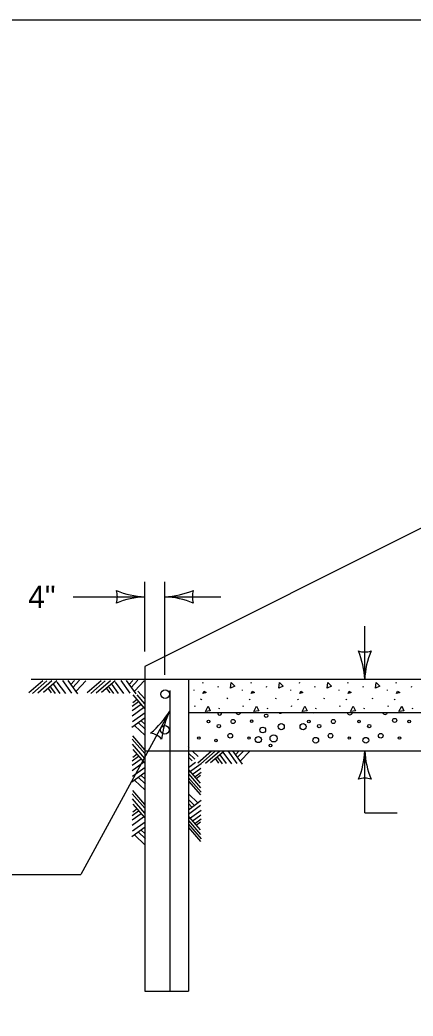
# Model space of a CAD drawing. Extents: x 49991.4 to 50021, y 49987.6 to 50011.4.
# Drawn here: x 50011.844 to 50012.898, y 49989.416 to 49992.087 of the extents above; entities that cross this region are included whole.
import ezdxf

# ---------------------------------------------------------------- set-up
doc = ezdxf.new("R2010")
doc.units = 0
for name, color, linetype in [('Level 1', 7, 'Continuous'), ('Level 2', 7, 'Continuous'), ('Level 3', 7, 'Continuous')]:
    doc.layers.add(name, color=color, linetype=linetype)

msp = doc.modelspace()

# ---------------------------------------------------------------- linework, layer by layer
at = {"layer": 'Level 1'}
for p, q in [((50013.9584, 49991.2434), (50012.1786, 49990.3535)), ((50012.1786, 49990.3535), (50012.1786, 49989.4831)), ((50011.9052, 49990.3145), (50011.8682, 49990.2823)), ((50011.8745, 49990.3188), (50012.2956, 49990.3188)), ((50011.9161, 49990.3145), (50011.8772, 49990.2806)), ((50011.9299, 49990.3147), (50011.8919, 49990.2816)), ((50011.9431, 49990.3149), (50011.9068, 49990.2833)), ((50011.9336, 49990.305), (50011.9509, 49990.2812)), ((50011.9432, 49990.3115), (50011.9658, 49990.2806)), ((50011.9579, 49990.3153), (50011.9824, 49990.2816)), ((50011.9722, 49990.3155), (50011.9982, 49990.2798)), ((50011.9792, 49990.304), (50011.99, 49990.3155)), ((50011.9857, 49990.2972), (50012.004, 49990.3165)), ((50011.9952, 49990.2881), (50012.0206, 49990.3151)), ((50012.0616, 49990.3145), (50012.0245, 49990.2823)), ((50012.0725, 49990.3145), (50012.0336, 49990.2806)), ((50012.0863, 49990.3147), (50012.0482, 49990.2816)), ((50012.0995, 49990.3149), (50012.063, 49990.2833)), ((50012.0899, 49990.305), (50012.1073, 49990.2812)), ((50012.0995, 49990.3115), (50012.122, 49990.2806)), ((50012.1141, 49990.3153), (50012.1387, 49990.2816)), ((50012.1284, 49990.3155), (50012.1546, 49990.2798)), ((50012.1355, 49990.304), (50012.1463, 49990.3155)), ((50012.142, 49990.2972), (50012.1602, 49990.3165)), ((50012.1516, 49990.2881), (50012.177, 49990.3151)), ((50012.1786, 49990.3145), (50012.1786, 49990.3145)), ((50012.2956, 49990.3188), (50012.2956, 49989.4831)), ((50012.2956, 49990.3188), (50014.2581, 49990.3188)), ((50011.9196, 49990.2939), (50011.9281, 49990.2822)), ((50011.9258, 49990.2978), (50011.9383, 49990.2806)), ((50012.076, 49990.2939), (50012.0845, 49990.2822)), ((50012.0822, 49990.2978), (50012.0947, 49990.2806)), ((50012.179, 49990.241), (50012.1474, 49990.2774)), ((50012.1788, 49990.2534), (50012.1583, 49990.2769)), ((50012.1786, 49990.2662), (50012.1604, 49990.2871)), ((50012.2454, 49990.2888), (50012.2454, 49989.4831)), ((50012.2956, 49990.279), (50012.2956, 49990.279)), ((50012.1618, 49990.2588), (50012.1447, 49990.2462)), ((50012.169, 49990.2516), (50012.1452, 49990.2343)), ((50012.1579, 49990.2644), (50012.1463, 49990.2559)), ((50012.1756, 49990.2428), (50012.1447, 49990.2203)), ((50012.1793, 49990.2291), (50012.1457, 49990.2045)), ((50012.2956, 49990.2297), (50014.2581, 49990.2297)), ((50012.1796, 49990.2157), (50012.1439, 49990.1897)), ((50012.1522, 49990.1941), (50012.179, 49990.1687)), ((50012.1613, 49990.2029), (50012.1806, 49990.1845)), ((50012.1681, 49990.2086), (50012.1795, 49990.1978)), ((50012.1786, 49990.13), (50012.1463, 49990.167)), ((50012.1786, 49990.1197), (50012.1447, 49990.1586)), ((50012.1788, 49990.1067), (50012.1457, 49990.1448)), ((50012.1618, 49990.1123), (50012.1447, 49990.0997)), ((50012.1579, 49990.1179), (50012.1463, 49990.1094)), ((50012.179, 49990.0945), (50012.1474, 49990.1309)), ((50012.1786, 49990.1273), (50014.2581, 49990.1273)), ((50012.3128, 49990.1049), (50012.2956, 49990.1212)), ((50012.322, 49990.1119), (50012.3057, 49990.1273)), ((50012.3576, 49990.1262), (50012.3206, 49990.0939)), ((50012.3674, 49990.1262), (50012.3285, 49990.0922)), ((50012.3797, 49990.1263), (50012.3416, 49990.0932)), ((50012.3913, 49990.1266), (50012.3549, 49990.0948)), ((50012.3799, 49990.1166), (50012.3972, 49990.0928)), ((50012.3882, 49990.1232), (50012.4107, 49990.0923)), ((50012.4011, 49990.1269), (50012.4256, 49990.0933)), ((50012.4137, 49990.1271), (50012.4398, 49990.0915)), ((50012.4208, 49990.1157), (50012.4316, 49990.1271)), ((50012.4262, 49990.1088), (50012.4437, 49990.1273)), ((50012.4343, 49990.0996), (50012.4598, 49990.1266)), ((50012.1756, 49990.0962), (50012.1447, 49990.0736)), ((50012.169, 49990.1051), (50012.1452, 49990.0878)), ((50012.306, 49990.1005), (50012.2956, 49990.1104)), ((50012.2956, 49990.0826), (50012.3145, 49990.0964)), ((50012.2986, 49990.0706), (50012.3294, 49990.0931)), ((50012.3679, 49990.1055), (50012.3764, 49990.0939)), ((50012.3733, 49990.1094), (50012.3858, 49990.0922)), ((50012.1796, 49990.0692), (50012.1439, 49990.0431)), ((50012.1793, 49990.0825), (50012.1457, 49990.058)), ((50012.1681, 49990.0621), (50012.1795, 49990.0513)), ((50012.2956, 49990.0758), (50012.3268, 49990.04)), ((50012.2956, 49990.0658), (50012.3284, 49990.028)), ((50012.3052, 49990.0634), (50012.3289, 49990.0807)), ((50012.3124, 49990.0577), (50012.3294, 49990.0701)), ((50012.3162, 49990.0531), (50012.3278, 49990.0616)), ((50012.1522, 49990.0476), (50012.179, 49990.0221)), ((50012.1613, 49990.0562), (50012.1806, 49990.038)), ((50012.2956, 49990.055), (50012.3294, 49990.0163)), ((50012.2956, 49990.0461), (50012.3278, 49990.0092)), ((50012.1786, 49989.9732), (50012.1447, 49990.0121)), ((50012.1786, 49989.9835), (50012.1463, 49990.0205)), ((50012.322, 49989.9869), (50012.2956, 49990.0118)), ((50012.1788, 49989.9602), (50012.1457, 49989.9983)), ((50012.179, 49989.948), (50012.1474, 49989.9843)), ((50012.3128, 49989.98), (50012.2956, 49989.9963)), ((50012.2956, 49989.9692), (50012.3302, 49989.9944)), ((50012.306, 49989.9756), (50012.2956, 49989.9855)), ((50012.2956, 49989.9577), (50012.3284, 49989.9817)), ((50012.1618, 49989.9656), (50012.1447, 49989.9531)), ((50012.169, 49989.9585), (50012.1452, 49989.9411)), ((50012.1579, 49989.9714), (50012.1463, 49989.9629)), ((50012.2986, 49989.9456), (50012.3294, 49989.9681)), ((50012.3052, 49989.9384), (50012.3289, 49989.9558)), ((50012.1756, 49989.9497), (50012.1447, 49989.9271)), ((50012.1793, 49989.936), (50012.1457, 49989.9115)), ((50012.2956, 49989.9509), (50012.3268, 49989.915)), ((50012.2956, 49989.9407), (50012.3284, 49989.903)), ((50012.2956, 49989.9301), (50012.3294, 49989.8912)), ((50012.3124, 49989.9327), (50012.3294, 49989.9452)), ((50012.3162, 49989.9282), (50012.3278, 49989.9367)), ((50012.1796, 49989.9227), (50012.1439, 49989.8966)), ((50012.1522, 49989.9011), (50012.179, 49989.8755)), ((50012.1613, 49989.9097), (50012.1806, 49989.8915)), ((50012.1681, 49989.9156), (50012.1795, 49989.9048)), ((50012.2956, 49989.9212), (50012.3278, 49989.8841)), ((50012.1786, 49989.7217), (50012.1786, 49989.7217)), ((50012.1786, 49989.4831), (50012.2956, 49989.4831))]:
    msp.add_line(p, q, dxfattribs=at)
msp.add_lwpolyline([(49999.5517, 49992.0867), (50014.5753, 49992.0867), (50014.5753, 49988.387), (49999.5517, 49988.387)], close=True, dxfattribs=at)
for centre, radius in [((50012.233, 49990.2792), 0.0116), ((50012.504, 49990.2212), 0.0046), ((50012.2325, 49990.1836), 0.0116), ((50012.3496, 49990.2058), 0.00341), ((50012.3771, 49990.1935), 0.0046), ((50012.4154, 49990.2058), 0.00552), ((50012.4651, 49990.2066), 0.00341), ((50012.5443, 49990.192), 0.00824), ((50012.6031, 49990.192), 0.00824), ((50012.6184, 49990.2058), 0.00341), ((50012.646, 49990.1935), 0.0046), ((50012.6843, 49990.2058), 0.00552), ((50012.7529, 49990.2058), 0.00341), ((50012.7804, 49990.1935), 0.0046), ((50012.8484, 49990.2086), 0.00552), ((50012.8873, 49990.2058), 0.00341), ((50012.3235, 49990.1615), 0.00341), ((50012.4077, 49990.1676), 0.00613), ((50012.458, 49990.1615), 0.00341), ((50012.4832, 49990.1573), 0.00824), ((50012.4948, 49990.183), 0.00766), ((50012.524, 49990.1605), 0.00968), ((50012.6766, 49990.1676), 0.00613), ((50012.7268, 49990.1615), 0.00341), ((50012.8111, 49990.1676), 0.00613), ((50012.8613, 49990.1615), 0.00341), ((50012.3695, 49990.1548), 0.00341), ((50012.5155, 49990.1413), 0.00341), ((50012.6368, 49990.1554), 0.00766), ((50012.7712, 49990.1554), 0.00766)]:
    msp.add_circle(centre, radius, dxfattribs=at)
for centre, radius, start, end in [((50012.3794, 49990.2286), 0.00552, 168.5096, 11.4904), ((50012.4296, 49990.2326), 0.00765, 202.8197, 337.1803), ((50012.5423, 49990.2334), 0.00552, 222.7241, 317.2759), ((50012.6305, 49990.2355), 0.00684, 238.3741, 301.6259), ((50012.7284, 49990.2317), 0.00765, 195.3909, 344.6091), ((50012.8228, 49990.2326), 0.00765, 202.8197, 337.1803), ((50012.2902, 49990.134), 0.00765, 14.7763, 45.1363)]:
    msp.add_arc(centre, radius, start, end, dxfattribs=at)
at = {"layer": 'Level 3'}
for p, q in [((50012.1786, 49990.3935), (50012.1786, 49990.5801)), ((50012.2327, 49990.3308), (50012.2327, 49990.5801)), ((50011.987, 49990.5401), (50012.1786, 49990.5401)), ((50012.2327, 49990.5401), (50012.3827, 49990.5401)), ((50012.7683, 49990.3188), (50012.7683, 49990.4617)), ((50012.334, 49990.3089), (50012.3351, 49990.3113)), ((50012.3752, 49990.2978), (50012.3763, 49990.3002)), ((50012.4637, 49990.3089), (50012.4648, 49990.3113)), ((50012.5048, 49990.2978), (50012.5059, 49990.3002)), ((50012.5934, 49990.3089), (50012.5944, 49990.3113)), ((50012.6345, 49990.2978), (50012.6356, 49990.3002)), ((50012.723, 49990.3089), (50012.7241, 49990.3113)), ((50012.7642, 49990.2978), (50012.7652, 49990.3002)), ((50012.8527, 49990.3089), (50012.8537, 49990.3113)), ((50012.8938, 49990.2978), (50012.8949, 49990.3002)), ((50012.3099, 49990.291), (50012.3102, 49990.2885)), ((50012.4395, 49990.291), (50012.4398, 49990.2885)), ((50012.5692, 49990.291), (50012.5695, 49990.2885)), ((50012.6988, 49990.291), (50012.6991, 49990.2885)), ((50012.8285, 49990.291), (50012.8288, 49990.2885)), ((50012.3124, 49990.2463), (50012.3135, 49990.2487)), ((50012.3284, 49990.2664), (50012.3294, 49990.2647)), ((50012.3294, 49990.2658), (50012.3305, 49990.2641)), ((50012.3998, 49990.2664), (50012.4009, 49990.2688)), ((50012.442, 49990.2463), (50012.4431, 49990.2487)), ((50012.458, 49990.2664), (50012.4591, 49990.2647)), ((50012.4591, 49990.2658), (50012.4602, 49990.2641)), ((50012.5295, 49990.2664), (50012.5306, 49990.2688)), ((50012.5717, 49990.2463), (50012.5728, 49990.2487)), ((50012.5877, 49990.2664), (50012.5888, 49990.2647)), ((50012.5888, 49990.2658), (50012.5898, 49990.2641)), ((50012.6591, 49990.2664), (50012.6602, 49990.2688)), ((50012.7014, 49990.2463), (50012.7024, 49990.2487)), ((50012.7173, 49990.2664), (50012.7184, 49990.2647)), ((50012.7184, 49990.2658), (50012.7195, 49990.2641)), ((50012.7888, 49990.2664), (50012.7899, 49990.2688)), ((50012.831, 49990.2463), (50012.8321, 49990.2487)), ((50012.847, 49990.2664), (50012.8481, 49990.2647)), ((50012.8481, 49990.2658), (50012.8491, 49990.2641)), ((50012.2454, 49990.2336), (50012.0072, 49989.7954)), ((50012.3779, 49990.2401), (50012.379, 49990.2425)), ((50012.5075, 49990.2401), (50012.5086, 49990.2425)), ((50012.6372, 49990.2401), (50012.6383, 49990.2425)), ((50012.7669, 49990.2401), (50012.7679, 49990.2425)), ((50012.8965, 49990.2401), (50012.8976, 49990.2425)), ((50012.7683, 49989.9608), (50012.7683, 49990.1273)), ((50012.7683, 49989.9608), (50012.8548, 49989.9608)), ((50011.7624, 49989.7954), (50012.0072, 49989.7954))]:
    msp.add_line(p, q, dxfattribs=at)
for points in [[(50012.4081, 49990.295), (50012.4103, 49990.3104), (50012.42, 49990.3004), (50012.4084, 49990.2951)], [(50012.5378, 49990.295), (50012.5399, 49990.3104), (50012.5496, 49990.3004), (50012.538, 49990.2951)], [(50012.6674, 49990.295), (50012.6696, 49990.3104), (50012.6793, 49990.3004), (50012.6677, 49990.2951)], [(50012.7971, 49990.295), (50012.7992, 49990.3104), (50012.8089, 49990.3004), (50012.7973, 49990.2951)], [(50012.3346, 49990.2804), (50012.3378, 49990.2872), (50012.3432, 49990.2832), (50012.3346, 49990.2804)], [(50012.4642, 49990.2804), (50012.4675, 49990.2872), (50012.4729, 49990.2832), (50012.4642, 49990.2804)], [(50012.5939, 49990.2804), (50012.5971, 49990.2872), (50012.6026, 49990.2832), (50012.5939, 49990.2804)], [(50012.7236, 49990.2804), (50012.7268, 49990.2872), (50012.7322, 49990.2832), (50012.7236, 49990.2804)], [(50012.8532, 49990.2804), (50012.8565, 49990.2872), (50012.8619, 49990.2832), (50012.8532, 49990.2804)], [(50012.3414, 49990.2328), (50012.3487, 49990.2466), (50012.3543, 49990.2339), (50012.3416, 49990.2328)], [(50012.471, 49990.2328), (50012.4783, 49990.2466), (50012.484, 49990.2339), (50012.4713, 49990.2328)], [(50012.6007, 49990.2328), (50012.608, 49990.2466), (50012.6137, 49990.2339), (50012.6009, 49990.2328)], [(50012.7303, 49990.2328), (50012.7376, 49990.2466), (50012.7433, 49990.2339), (50012.7306, 49990.2328)], [(50012.86, 49990.2328), (50012.8673, 49990.2466), (50012.873, 49990.2339), (50012.8602, 49990.2328)]]:
    msp.add_lwpolyline(points, dxfattribs=at)
for centre, radius, start, end in [((50012.1878, 49990.7622), 0.2223, 247.456, 267.6395), ((50012.0504, 49990.5401), 0.0548, 342.1388, 17.8612), ((50012.1901, 49990.3073), 0.233, 92.8273, 112.0772), ((50012.2212, 49990.7728), 0.233, 272.8273, 292.0772), ((50012.2235, 49990.3179), 0.2223, 67.456, 87.6395), ((50012.3609, 49990.5401), 0.0548, 162.1388, 197.8612), ((50012.7683, 49990.447), 0.0548, 252.1388, 287.8612), ((50012.5356, 49990.3073), 0.233, 2.8273, 22.0772), ((50012.9904, 49990.3096), 0.2223, 157.456, 177.6395), ((50012.0546, 49990.3477), 0.2223, 308.9255, 329.109), ((50012.4553, 49990.1325), 0.233, 154.2968, 173.5466), ((50012.1842, 49990.1209), 0.0548, 43.6083, 79.3306), ((50012.5462, 49990.1364), 0.2223, 337.456, 357.6395), ((50013.001, 49990.1387), 0.233, 182.8273, 202.0772), ((50012.7683, 49989.999), 0.0548, 72.1388, 107.8612)]:
    msp.add_arc(centre, radius, start, end, dxfattribs=at)

# ---------------------------------------------------------------- texts
at = {"layer": 'Level 2'}
msp.add_text('4"', height=0.06, dxfattribs=at).set_placement((50011.8663, 49990.5101))

doc.saveas('drawing.dxf')
